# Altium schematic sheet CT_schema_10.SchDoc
size 391 x 238 mm
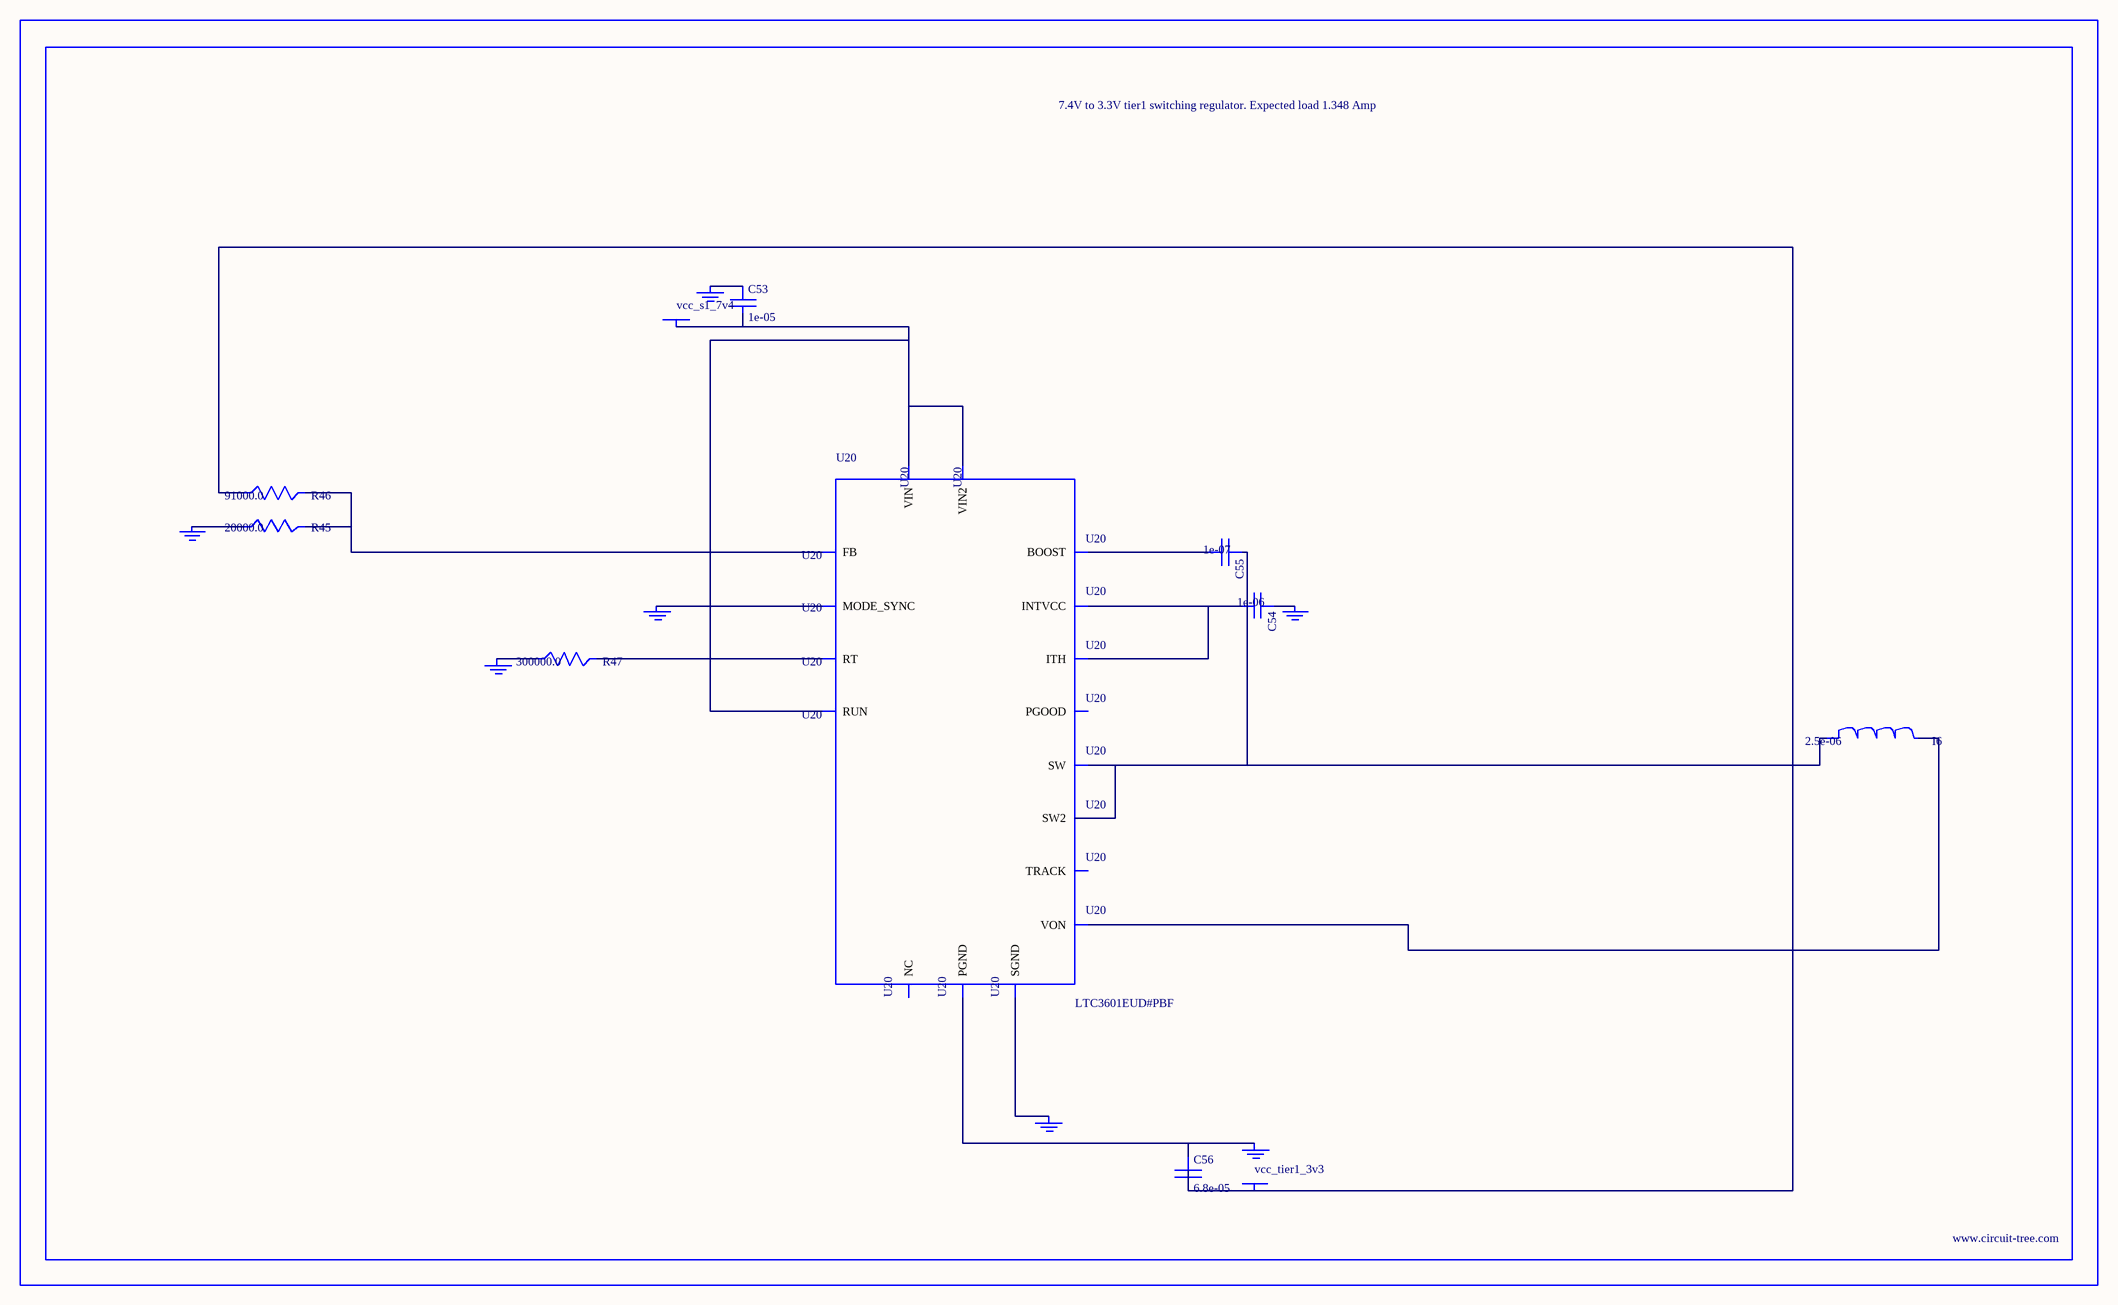
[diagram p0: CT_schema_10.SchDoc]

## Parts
BORDER9  (no value)
C53  1e-05  [C0805]
C54  1e-06  [C0603]
C55  1e-07  [C0402]
C56  6.8e-05  [2220]
GND_INSTANCE_9_0  (no value)
GND_INSTANCE_9_1  (no value)
GND_INSTANCE_9_2  (no value)
GND_INSTANCE_9_3  (no value)
GND_INSTANCE_9_4  (no value)
GND_INSTANCE_9_5  (no value)
GND_INSTANCE_9_6  (no value)
I6  2.5e-06  [DR1040]
POWER_INSTANCE_9_0  vcc_s1_7v4
POWER_INSTANCE_9_1  vcc_tier1_3v3
R45  20000.0  [R0603]
R46  91000.0  [R0603]
R47  300000.0  [R0603]
U20  LTC3601EUD#PBF  [QFN-16_EP]

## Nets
NetC53_1: C53.1 GND_INSTANCE_9_5.0(GND)
NetC53_2: C53.2 POWER_INSTANCE_9_0.0(PWR) U20.14(RUN) U20.15(VIN) U20.16(VIN2)
NetC54_1: C54.1 GND_INSTANCE_9_1.0(GND)
NetC54_2: C54.2 U20.7(INTVCC) U20.12(ITH)
NetC55_1: C55.1 I6.1 U20.3(SW) U20.4(SW2)
NetC55_2: C55.2 U20.6(BOOST)
NetC56_1: C56.1 GND_INSTANCE_9_6.0(GND) U20.17(PGND)
NetC56_2: C56.2 I6.2 POWER_INSTANCE_9_1.0(PWR) R46.1 U20.8(VON)
NetGND_INSTANCE_9_0_0: GND_INSTANCE_9_0.0(GND) U20.1(MODE_SYNC)
NetGND_INSTANCE_9_2_0: GND_INSTANCE_9_2.0(GND) U20.9(SGND)
NetGND_INSTANCE_9_3_0: GND_INSTANCE_9_3.0(GND) R47.1
NetGND_INSTANCE_9_4_0: GND_INSTANCE_9_4.0(GND) R45.1
NetR45_2: R45.2 R46.2 U20.11(FB)
NetR47_2: R47.2 U20.10(RT)

Not connected (* = marked no-connect by the designer): U20 2(PGOOD) 5(NC) 13(TRACK)

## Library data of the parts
BORDER9 = BORDER_PAGE9
C53 = C0805C106K8RACTU
C54 = C0603C105K3RACTU
C55 = C0402C104K3RACTU
C56 = C5750X5R1A686M
GND_INSTANCE_9_0-GND_INSTANCE_9_6 = GND
I6 = DR1040-2R5-R
POWER_INSTANCE_9_0 POWER_INSTANCE_9_1 = PWR
R45 = RC0603JR-0720KL
R46 = RC0603JR-0791KL
R47 = RC0603JR-07300KL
